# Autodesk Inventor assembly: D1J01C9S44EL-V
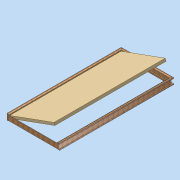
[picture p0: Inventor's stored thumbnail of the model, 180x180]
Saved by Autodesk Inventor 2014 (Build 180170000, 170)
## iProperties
Created: 2012-07
Part Number: D1J01C9S44EL-V
Document SubType Name: Assembly
Designer: david.appleford
Mass: 35000 g
Surface Area: 54366.8 cm^2
Volume: 91650.3 cm^3
Density: 0.381886 g/cm^3
Description: Door Frame 1 Width Style J01 LH
Cost Center: £369.00
Justset: False
Author: david.appleford
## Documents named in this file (3)
- C:\Documents and Settings\john.everitt\Local Settings\My Documents\Vault\Production MkII\VIRTUAL ELEMENTS\Virtual Doors\Star Projects\D1J01C9S44EL-V.iam
- C:\Documents and Settings\john.everitt\Local Settings\My Documents\Vault\Production MkII\Virtual Elements\Virtual Doors\Star Projects\D1J01C9S44-V.ipt
- C:\Documents and Settings\john.everitt\Local Settings\My Documents\Vault\Production MkII\VIRTUAL ELEMENTS\Virtual Doors\D44J01E-V.ipt
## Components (2 placed, 2 different names)
1. D1J01C9S44-V:1 — Mate:1, Mate:2, Mate:3, Angle:1
2. D44J01E-V:1 — Mate:1, Mate:2, Mate:3, Angle:1
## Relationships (4: Mate 3, Angle 1)
- Mate:1: D1J01C9S44-V:1 ↔ D44J01E-V:1
- Mate:2: D1J01C9S44-V:1 ↔ D44J01E-V:1
- Mate:3: D1J01C9S44-V:1 ↔ D44J01E-V:1
- Angle:1: D1J01C9S44-V:1 ↔ D44J01E-V:1
